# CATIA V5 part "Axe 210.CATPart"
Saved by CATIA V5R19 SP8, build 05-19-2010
Part number: Axe 210
Bounding box of the stored display mesh (mm): x 0 to 210, y -15 to 15, z -15 to 15
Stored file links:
  J:\Travail\2e année\IAO\Projet\Axe 210.CATPart
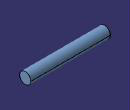
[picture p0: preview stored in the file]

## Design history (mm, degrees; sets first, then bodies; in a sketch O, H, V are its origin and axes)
Body1 (main body)
  Sketch1 on yz-plane, origin (0, 0, 0), H (0, 1, 0), V (0, 0, 1)
    circle A1 centre (0, 0) radius 15
    radius A1 = 15
  Pad1: profile Sketch1, direction (1, 0, 0), length 210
